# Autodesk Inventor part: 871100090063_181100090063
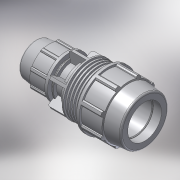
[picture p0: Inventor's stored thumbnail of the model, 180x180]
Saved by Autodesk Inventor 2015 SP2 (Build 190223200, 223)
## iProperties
Created: 2017-02
Part Number: 871100090063_181100090063
Material: PVC-Piping
Description: PLASSON REDUCING COUPLER 90-63
Document SubType Name: Modeling
Designer: KIM
Mass: 92.6774 g
Surface Area: 199.44 cm^2
Volume: 66.1981 cm^3
Density: 1.4 g/cm^3
Appearance: Smooth - White
Author: KIM
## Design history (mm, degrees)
derived "87110.ipt"
feature "Solid1::87110.ipt"
tag "TaggingFeature1"
body "Solid1"
other parameters: "d4" = 24.25, "d5" = 41.57143, "d7" = 152, "d9" = 41.57143, "d11" = 4.15714, "d12" = 121.6, "d13" = 120 deg, "d14" = 126, "d15" = 6 deg, "d16" = 136.8, "d18" = 4.5, "d19" = 35 deg, "d20" = 17.5 deg, "d21" = 141.36, "d23" = 0, "d25" = 360 deg, "d27" = 3.04, "d42" = 64.02, "d46" = 1.8, "d51" = 291, "d52" = 41.57143, "d53" = 8 deg, "d54" = 169, "d56" = 88.2, "d57" = 63, "d58" = 81, "d59" = 56.7, "d60" = 101.7, "d61" = 90.4, "d62" = 36.375, "d63" = 52.38, "d64" = 120 deg, "d65" = 113, "d68" = 20.78571, "d74" = 105.09, "d75" = 35 deg, "d76" = 17.5 deg, "d78" = 0, "d80" = 360 deg, "d85" = 2.26, "d88" = 1.26, "d93" = 115, "d94" = 106.4, "d98" = 7.53333, "d99" = 0, "d100" = 6.08, "d102" = 360 deg, "d104" = 2, "d106" = 0, "d107" = 7.53333, "d108" = 0, "d109" = 7.53333, "d110" = 0, "d111" = 3.18333, "d112" = 3.18333, "d113" = 3.18333, "d114" = 4.19657, "d116" = 4.19657, "d119" = 8.39314, "d125" = 134.064, "E_" = 152, "H_" = 291, "l_" = 169, "d_1" = 63, "E_1" = 113, "l_1" = 115, "d96" = 9.55, "d115" = 41.96571
